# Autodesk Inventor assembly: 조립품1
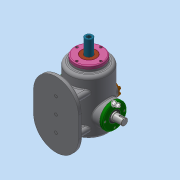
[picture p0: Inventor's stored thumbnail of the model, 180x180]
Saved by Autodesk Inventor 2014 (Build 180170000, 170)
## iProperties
Created: 2022-08
Part Number: 조립품1
Document SubType Name: Assembly
Designer: dg
Mass: 8316.85 g
Surface Area: 4266.62 cm^2
Volume: 2093.19 cm^3
Density: 3.97329 g/cm^3
Author: dg
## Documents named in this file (16)
- C:\Users\dg\Desktop\620806V1006\조립품1.iam
- C:\Users\dg\Desktop\620806V1006\본체.ipt
- C:\Users\dg\Desktop\620806V1006\베어링 6205.ipt
- 베어링 6205.ipt
- C:\Users\dg\Desktop\620806V1006\볼트 M4x0.7.ipt
- C:\Users\dg\Desktop\620806V1006\부시.ipt
- C:\Users\dg\Desktop\620806V1006\상부 캡.ipt
- C:\Users\dg\Desktop\620806V1006\슬라이드 커버.ipt
- C:\Users\dg\Desktop\620806V1006\슬라이드.ipt
- C:\Users\dg\Desktop\620806V1006\오일실.ipt
- 오일실.ipt
- C:\Users\dg\Desktop\620806V1006\축 커버-1.ipt
- C:\Users\dg\Desktop\620806V1006\축 커버-2.ipt
- C:\Users\dg\Desktop\620806V1006\편심축.ipt
- C:\Users\dg\Desktop\620806V1006\플레이트.ipt
- C:\Users\dg\Desktop\620806V1006\가변스프링.ipt
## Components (14 placed, 3 different names)
1. M4x0.7:1
2. 플레이트:1
3. M4x0.7:2
4. M4x0.7:3
5. M4x0.7:4
6. M4x0.7:5
7. M4x0.7:6
8. M4x0.7:7
9. M4x0.7:8
10. M4x0.7:9
11. M4x0.7:10
12. M4x0.7:11
13. M4x0.7:12
14. 가변스프링:1
